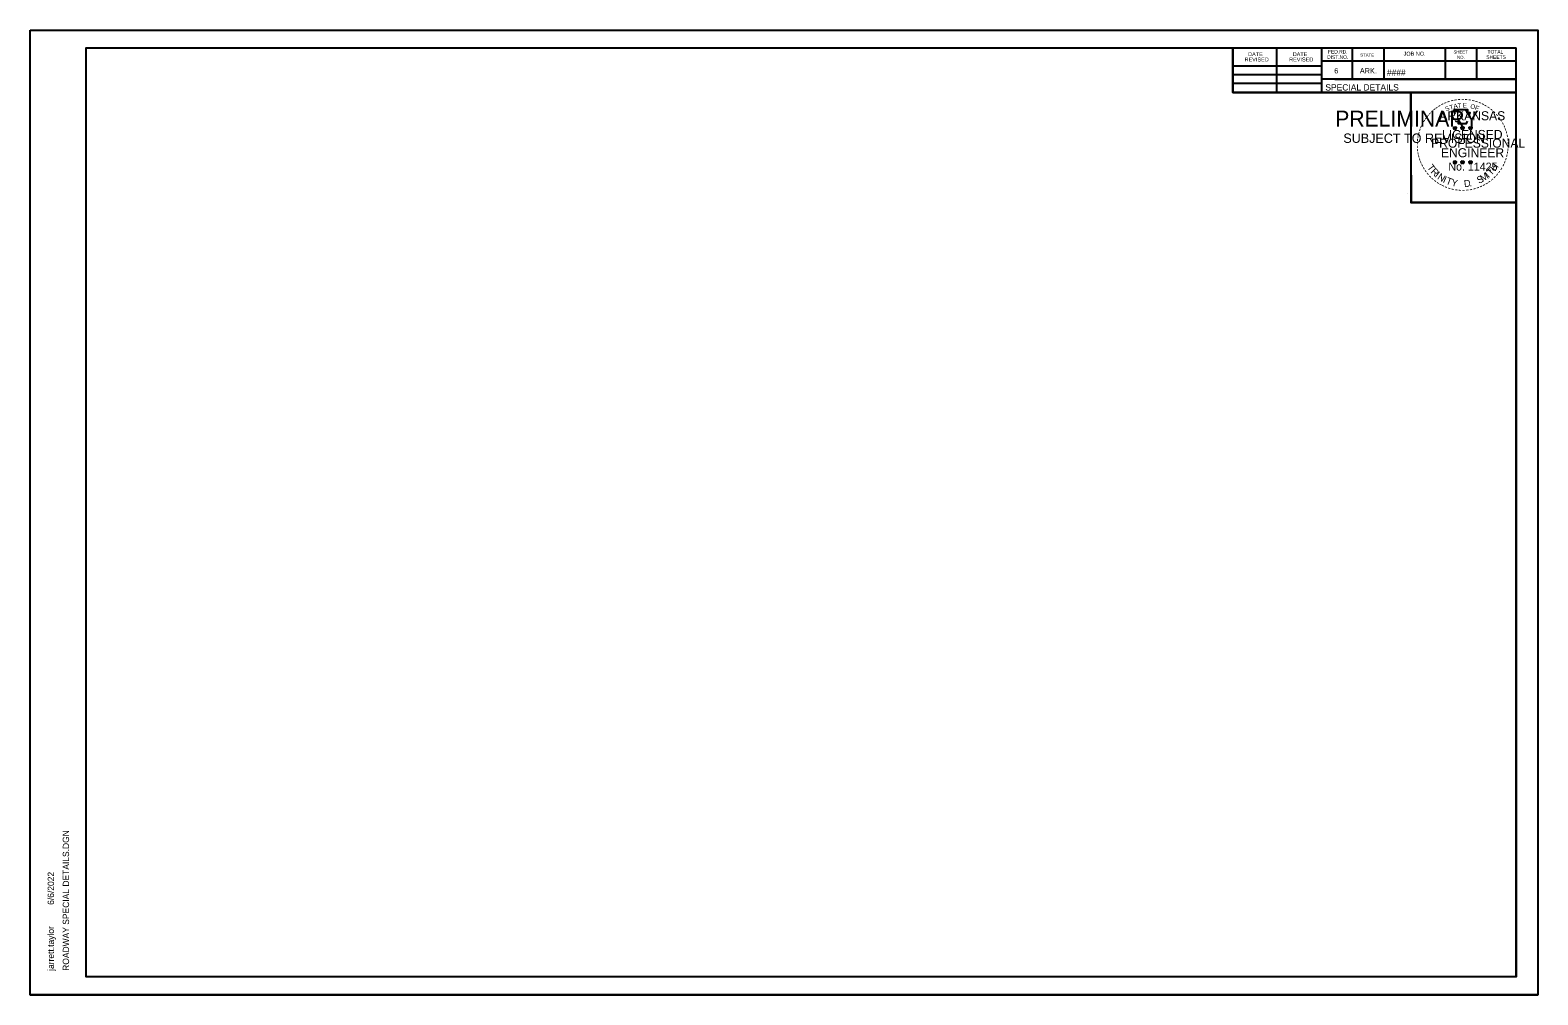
# Model space of a CAD drawing. Extents: x 438659 to 573674, y 10724 to 98600.
# Drawn here: x 532438.7 to 532605.4, y 52572.9 to 52679.6 of the extents above; entities that cross this region are included whole.
import ezdxf

# ---------------------------------------------------------------- set-up
doc = ezdxf.new("R2010")
doc.units = 0
for name, color, linetype in [('R_Grid', 7, 'Continuous'), ('R_Horz Alg', 7, 'Continuous'), ('R_Horz Alg Annot', 7, 'Continuous'), ('R_MOT', 7, 'Continuous')]:
    doc.layers.add(name, color=color, linetype=linetype)

msp = doc.modelspace()

# ---------------------------------------------------------------- linework, layer by layer
at = {"layer": 'R_Grid'}
for p, q in [((532444.94, 52677.62), (532603.03, 52677.62)), ((532444.94, 52574.89), (532444.94, 52677.62)), ((532521.2, 52677.49), (532521.2, 52677.49)), ((532521.2, 52677.49), (532521.2, 52677.49)), ((532571.71, 52672.68), (532571.71, 52677.62)), ((532576.55, 52672.68), (532576.55, 52677.62)), ((532581.48, 52677.62), (532581.48, 52672.68)), ((532584.9, 52677.62), (532584.9, 52674.15)), ((532588.37, 52677.62), (532588.37, 52674.15)), ((532595.16, 52677.62), (532595.16, 52674.15)), ((532598.63, 52677.62), (532598.63, 52674.15)), ((532603.03, 52574.89), (532603.03, 52677.62)), ((532603.03, 52676.15), (532581.48, 52676.15)), ((532603.03, 52676.16), (532603.03, 52676.16)), ((532571.71, 52675.61), (532581.48, 52675.61)), ((532571.71, 52674.68), (532581.48, 52674.68)), ((532603.03, 52674.15), (532581.48, 52674.15)), ((532582.96, 52674.15), (532603.03, 52674.15)), ((532571.71, 52673.71), (532581.48, 52673.71)), ((532603.03, 52672.68), (532571.71, 52672.68)), ((532444.94, 52574.89), (532444.94, 52574.89)), ((532603.03, 52574.89), (532444.94, 52574.89))]:
    msp.add_line(p, q, dxfattribs=at)
at = {"layer": 'R_Horz Alg'}
for p, q in [((532438.74, 52679.57), (532605.41, 52679.57)), ((532591.05, 52661.45), (532591.05, 52661.45)), ((532438.74, 52572.9), (532605.41, 52572.9))]:
    msp.add_line(p, q, dxfattribs=at)
for points in [[(532438.74, 52679.57), (532605.41, 52679.57), (532605.41, 52572.89), (532438.74, 52572.89)], [(532561.9, 52677.62), (532571.71, 52677.62), (532571.71, 52672.68), (532579.77, 52672.68), (532591.37, 52672.68), (532591.37, 52660.51), (532603.03, 52660.51), (532603.03, 52574.89), (532444.94, 52574.89), (532444.94, 52677.62)], [(532591.37, 52672.68), (532602.97, 52672.68), (532603.03, 52660.51), (532591.43, 52660.51)]]:
    msp.add_lwpolyline(points, close=True, dxfattribs=at)
at = {"layer": 'R_MOT'}
for p, q in [((532596.08, 52668.81), (532596.25, 52668.75)), ((532596.08, 52668.81), (532596.2, 52668.78)), ((532596.08, 52668.81), (532596.2, 52668.75)), ((532596.14, 52668.6), (532596.25, 52668.75)), ((532596.14, 52668.6), (532596.21, 52668.72)), ((532596.14, 52668.6), (532596.25, 52668.71)), ((532596.25, 52668.93), (532596.23, 52668.81)), ((532596.25, 52668.75), (532596.25, 52668.93)), ((532596.25, 52668.93), (532596.28, 52668.81)), ((532596.42, 52668.81), (532596.25, 52668.75)), ((532596.36, 52668.6), (532596.25, 52668.75)), ((532596.36, 52668.6), (532596.25, 52668.71)), ((532596.42, 52668.81), (532596.28, 52668.78)), ((532596.36, 52668.6), (532596.29, 52668.75)), ((532596.42, 52668.81), (532596.32, 52668.76)), ((532596.91, 52668.81), (532597.09, 52668.75)), ((532596.91, 52668.81), (532597.04, 52668.78)), ((532596.91, 52668.81), (532597.03, 52668.75)), ((532596.98, 52668.6), (532597.09, 52668.75)), ((532596.98, 52668.6), (532597.04, 52668.72)), ((532596.98, 52668.6), (532597.09, 52668.71)), ((532597.09, 52668.93), (532597.07, 52668.81)), ((532597.09, 52668.75), (532597.09, 52668.93)), ((532597.09, 52668.93), (532597.11, 52668.81)), ((532597.26, 52668.81), (532597.09, 52668.75)), ((532597.19, 52668.6), (532597.09, 52668.75)), ((532597.19, 52668.6), (532597.09, 52668.71)), ((532597.26, 52668.81), (532597.12, 52668.78)), ((532597.19, 52668.6), (532597.12, 52668.75)), ((532597.26, 52668.81), (532597.16, 52668.76)), ((532597.79, 52668.8), (532597.97, 52668.74)), ((532597.79, 52668.8), (532597.92, 52668.78)), ((532597.79, 52668.8), (532597.91, 52668.74)), ((532597.86, 52668.6), (532597.97, 52668.74)), ((532597.86, 52668.6), (532597.92, 52668.72)), ((532597.86, 52668.6), (532597.97, 52668.7)), ((532597.97, 52668.93), (532597.95, 52668.8)), ((532597.97, 52668.74), (532597.97, 52668.93)), ((532597.97, 52668.93), (532597.99, 52668.8)), ((532598.14, 52668.8), (532597.97, 52668.74)), ((532598.07, 52668.6), (532597.97, 52668.74)), ((532598.07, 52668.6), (532597.97, 52668.7)), ((532598.14, 52668.8), (532598, 52668.78)), ((532598.07, 52668.6), (532598.01, 52668.74)), ((532598.14, 52668.8), (532598.04, 52668.75)), ((532596.07, 52665.02), (532596.25, 52664.96)), ((532596.07, 52665.02), (532596.2, 52665)), ((532596.07, 52665.02), (532596.19, 52664.96)), ((532596.14, 52664.82), (532596.25, 52664.96)), ((532596.14, 52664.82), (532596.2, 52664.94)), ((532596.14, 52664.82), (532596.25, 52664.92)), ((532596.25, 52665.15), (532596.23, 52665.02)), ((532596.25, 52664.96), (532596.25, 52665.15)), ((532596.25, 52665.15), (532596.27, 52665.02)), ((532596.42, 52665.02), (532596.25, 52664.96)), ((532596.36, 52664.82), (532596.25, 52664.96)), ((532596.36, 52664.82), (532596.25, 52664.92)), ((532596.42, 52665.02), (532596.28, 52665)), ((532596.36, 52664.82), (532596.29, 52664.96)), ((532596.42, 52665.02), (532596.32, 52664.97)), ((532596.91, 52665.02), (532597.08, 52664.96)), ((532596.91, 52665.02), (532597.04, 52665)), ((532596.91, 52665.02), (532597.03, 52664.96)), ((532596.98, 52664.82), (532597.08, 52664.96)), ((532596.98, 52664.82), (532597.04, 52664.94)), ((532596.98, 52664.82), (532597.08, 52664.92)), ((532597.08, 52665.15), (532597.06, 52665.02)), ((532597.08, 52664.96), (532597.08, 52665.15)), ((532597.08, 52665.15), (532597.11, 52665.02)), ((532597.26, 52665.02), (532597.08, 52664.96)), ((532597.19, 52664.82), (532597.08, 52664.96)), ((532597.19, 52664.82), (532597.08, 52664.92)), ((532597.26, 52665.02), (532597.11, 52665)), ((532597.19, 52664.82), (532597.12, 52664.96)), ((532597.26, 52665.02), (532597.16, 52664.97)), ((532597.79, 52665.01), (532597.97, 52664.96)), ((532597.79, 52665.01), (532597.92, 52664.99)), ((532597.79, 52665.01), (532597.91, 52664.95)), ((532597.86, 52664.81), (532597.97, 52664.96)), ((532597.86, 52664.81), (532597.92, 52664.93)), ((532597.86, 52664.81), (532597.97, 52664.92)), ((532597.97, 52665.14), (532597.95, 52665.02)), ((532597.97, 52664.96), (532597.97, 52665.14)), ((532597.97, 52665.14), (532597.99, 52665.02)), ((532598.14, 52665.01), (532597.97, 52664.96)), ((532598.07, 52664.81), (532597.97, 52664.96)), ((532598.07, 52664.81), (532597.97, 52664.92)), ((532598.14, 52665.01), (532598, 52664.99)), ((532598.07, 52664.81), (532598.01, 52664.96)), ((532598.14, 52665.01), (532598.04, 52664.96))]:
    msp.add_line(p, q, dxfattribs=at)
for points in [[(532596.1, 52670.75), (532596.23, 52670.33)], [(532597.85, 52670.28), (532597.92, 52670.43), (532597.58, 52670.41), (532597.66, 52670.75), (532596.1, 52670.75)], [(532596.34, 52669.53), (532596.34, 52669.49), (532596.62, 52669.48), (532596.6, 52669.24), (532597.53, 52669.24), (532597.63, 52669.51)], [(532596.25, 52668.93), (532596.36, 52668.6), (532596.08, 52668.81), (532596.42, 52668.81), (532596.14, 52668.6), (532596.25, 52668.93)], [(532597.09, 52668.93), (532597.19, 52668.6), (532596.91, 52668.81), (532597.26, 52668.81), (532596.98, 52668.6), (532597.09, 52668.93)], [(532597.97, 52668.93), (532598.07, 52668.6), (532597.79, 52668.8), (532598.14, 52668.8), (532597.86, 52668.6), (532597.97, 52668.93)], [(532596.25, 52665.15), (532596.36, 52664.82), (532596.07, 52665.02), (532596.42, 52665.02), (532596.14, 52664.82), (532596.25, 52665.15)], [(532597.08, 52665.15), (532597.19, 52664.82), (532596.91, 52665.02), (532597.26, 52665.02), (532596.98, 52664.82), (532597.08, 52665.15)], [(532597.97, 52665.14), (532598.07, 52664.81), (532597.79, 52665.01), (532598.14, 52665.01), (532597.86, 52664.81), (532597.97, 52665.14)]]:
    msp.add_lwpolyline(points, dxfattribs=at)
for centre, radius in [((532596.25, 52668.75), 0.0861), ((532596.25, 52668.75), 0.0723), ((532596.25, 52668.75), 0.0579), ((532596.25, 52668.75), 0.0495), ((532596.25, 52668.75), 0.0374), ((532596.25, 52668.75), 0.0248), ((532596.25, 52668.75), 0.0148), ((532597.09, 52668.75), 0.0861), ((532597.09, 52668.75), 0.0723), ((532597.09, 52668.75), 0.0579), ((532597.09, 52668.75), 0.0495), ((532597.09, 52668.75), 0.0374), ((532597.09, 52668.75), 0.0248), ((532597.09, 52668.75), 0.0148), ((532597.97, 52668.74), 0.0861), ((532597.97, 52668.74), 0.0723), ((532597.97, 52668.74), 0.0579), ((532597.97, 52668.74), 0.0495), ((532597.97, 52668.74), 0.0374), ((532597.97, 52668.74), 0.0248), ((532597.97, 52668.74), 0.0148), ((532596.25, 52664.96), 0.0861), ((532596.25, 52664.96), 0.0723), ((532596.25, 52664.96), 0.0579), ((532596.25, 52664.96), 0.0495), ((532596.25, 52664.96), 0.0374), ((532596.25, 52664.96), 0.0248), ((532596.25, 52664.96), 0.0148), ((532597.08, 52664.96), 0.0861), ((532597.08, 52664.96), 0.0723), ((532597.08, 52664.96), 0.0579), ((532597.08, 52664.96), 0.0495), ((532597.08, 52664.96), 0.0374), ((532597.08, 52664.96), 0.0248), ((532597.08, 52664.96), 0.0148), ((532597.97, 52664.96), 0.0861), ((532597.97, 52664.96), 0.0723), ((532597.97, 52664.96), 0.0579), ((532597.97, 52664.96), 0.0495), ((532597.97, 52664.96), 0.0374), ((532597.97, 52664.96), 0.0248), ((532597.97, 52664.96), 0.0148)]:
    msp.add_circle(centre, radius, dxfattribs=at)

# ---------------------------------------------------------------- texts
at = {"layer": 'R_Grid'}
for s, height, p in [('REVISED', 0.44, (532572.99, 52676.1)), ('DATE', 0.44, (532573.38, 52676.69)), ('REVISED', 0.44, (532577.92, 52676.1)), ('DATE', 0.44, (532578.31, 52676.69)), ('DIST.NO.', 0.391, (532582.12, 52676.39)), ('FED.RD.', 0.391, (532582.22, 52676.98)), ('STATE', 0.342, (532585.78, 52676.64)), ('JOB NO.', 0.44, (532590.57, 52676.74)), ('SHEET', 0.342, (532596.09, 52676.98)), ('NO.', 0.342, (532596.48, 52676.39)), ('SHEETS', 0.391, (532599.71, 52676.39)), ('TOTAL', 0.391, (532599.85, 52676.98)), ('6', 0.586, (532582.9, 52674.78)), ('ARK.', 0.586, (532585.73, 52674.78)), ('####', 0.7, (532588.72, 52674.52)), ('SPECIAL DETAILS', 0.7, (532581.92, 52672.89))]:
    msp.add_text(s, height=height, dxfattribs=at).set_placement(p)
for s, p in [('ROADWAY SPECIAL DETAILS.DGN', (532443.04, 52575.55)), ('6/6/2022', (532441.37, 52582.85)), ('jarrett.taylor', (532441.37, 52575.55))]:
    msp.add_text(s, height=0.7, rotation=90, dxfattribs=at).set_placement(p)
at = {"layer": 'R_Horz Alg Annot'}
for s, height, p in [('PRELIMINARY', 1.75, (532583.01, 52668.91)), ('DWB', 0.005, (532583.38, 52669.83)), ('SUBJECT TO REVISION', 1.0376, (532583.91, 52667.1))]:
    msp.add_text(s, height=height, dxfattribs=at).set_placement(p)
at = {"layer": 'R_MOT'}
for s, height, rotation, p in [('-', 0.8, 38.9507, (532594.01, 52670.44)), ('-', 0.8, 36.2317, (532594.25, 52670.63)), ('-', 0.8, 34.0636, (532594.54, 52670.83)), ('-', 0.8, 28.7918, (532594.84, 52671.02)), ('-', 0.8, 24.3072, (532595.15, 52671.17)), ('S', 0.5, 21.594, (532595.27, 52670.58)), ('-', 0.8, 19.1761, (532595.47, 52671.31)), ('T', 0.5, 16.4036, (532595.73, 52670.75)), ('-', 0.8, 13.6302, (532595.85, 52671.43)), ('A', 0.5, 11.2132, (532596.14, 52670.88)), ('-', 0.8, 10.2193, (532596.19, 52671.51)), ('T', 0.5, 6.0228, (532596.57, 52670.96)), ('-', 0.8, 5.8968, (532596.55, 52671.57)), ('-', 0.8, 0.1862, (532596.94, 52671.6)), ('E', 0.5, 0.8323, (532597.12, 52671.01)), ('-', 0.8, 357.743, (532597.3, 52671.59)), ('-', 0.8, 352.1617, (532597.67, 52671.57)), ('O', 0.5, 350.4515, (532597.92, 52670.91)), ('-', 0.8, 347.2049, (532598.03, 52671.51)), ('F', 0.5, 340.0707, (532598.4, 52670.79)), ('-', 0.8, 342.3362, (532598.35, 52671.43)), ('-', 0.8, 337.8551, (532598.71, 52671.32)), ('-', 0.8, 334.1211, (532599.03, 52671.19)), ('-', 0.8, 329.6409, (532599.32, 52671.04)), ('-', 0.8, 325.8627, (532599.64, 52670.86)), ('-', 0.8, 320.5297, (532599.95, 52670.65)), ('-', 0.8, 62.8713, (532592.84, 52668.9)), ('-', 0.8, 58.0706, (532593, 52669.21)), ('-', 0.8, 54.2325, (532593.16, 52669.47)), ('-', 0.8, 50.6142, (532593.37, 52669.75)), ('-', 0.8, 48.4231, (532593.57, 52670)), ('-', 0.8, 42.9622, (532593.8, 52670.24)), ('-', 0.8, 315.5786, (532600.24, 52670.41)), ('-', 0.8, 309.8797, (532600.53, 52670.13)), ('-', 0.8, 306.6522, (532600.79, 52669.83)), ('-', 0.7, 303.6753, (532601.03, 52669.55)), ('-', 0.8, 299.6684, (532601.19, 52669.24)), ('-', 0.8, 85.1863, (532592.4, 52667.22)), ('-', 0.8, 81.2013, (532592.44, 52667.57)), ('-', 0.8, 75.461, (532592.51, 52667.92)), ('-', 0.8, 72.3945, (532592.61, 52668.28)), ('-', 0.8, 67.7743, (532592.71, 52668.59)), ('-', 0.8, 294.6628, (532601.36, 52668.94)), ('-', 0.8, 290.5728, (532601.48, 52668.65)), ('-', 0.8, 285.1233, (532601.6, 52668.36)), ('-', 0.8, 280.5493, (532601.7, 52667.99)), ('-', 0.8, 276.5962, (532601.78, 52667.6)), ('-', 0.8, 94.1959, (532592.41, 52666.51)), ('-', 0.8, 89.0622, (532592.39, 52666.87)), ('-', 0.8, 98.9479, (532592.44, 52666.17)), ('-', 0.8, 101.7149, (532592.51, 52665.81)), ('-', 0.8, 255.7626, (532601.73, 52665.93)), ('-', 0.8, 260.9953, (532601.78, 52666.27)), ('-', 0.8, 263.5172, (532601.82, 52666.59)), ('-', 0.8, 274.3301, (532601.81, 52667.24)), ('-', 0.8, 269.9407, (532601.83, 52666.93)), ('-', 0.8, 105.4578, (532592.59, 52665.51)), ('-', 0.8, 109.0874, (532592.7, 52665.19)), ('-', 0.8, 114.0643, (532592.83, 52664.9)), ('-', 0.8, 115.7289, (532592.98, 52664.59)), ('-', 0.8, 120.4471, (532593.16, 52664.29)), ('T', 0.77, 306.0406, (532593.13, 52664.38)), ('R', 0.77, 314.005, (532593.51, 52663.86)), ('T', 0.77, 46.6444, (532600.24, 52663.43)), ('H', 0.77, 54.6088, (532600.69, 52663.9)), ('-', 0.8, 239.0712, (532601.2, 52664.54)), ('-', 0.8, 244.6197, (532601.4, 52664.92)), ('-', 0.8, 247.8887, (532601.53, 52665.23)), ('-', 0.8, 252.8681, (532601.64, 52665.57)), ('-', 0.8, 125.8934, (532593.36, 52664.01)), ('-', 0.8, 130.7181, (532593.59, 52663.74)), ('-', 0.8, 134.2238, (532593.85, 52663.46)), ('-', 0.8, 138.9338, (532594.11, 52663.23)), ('-', 0.8, 144.6463, (532594.39, 52663.03)), ('I', 0.77, 321.9694, (532593.96, 52663.39)), ('-', 0.8, 148.0898, (532594.67, 52662.84)), ('N', 0.77, 326.5002, (532594.24, 52663.16)), ('-', 0.8, 151.5704, (532594.96, 52662.68)), ('I', 0.77, 335.3603, (532594.85, 52662.76)), ('T', 0.77, 339.8912, (532595.18, 52662.6)), ('Y', 0.77, 347.8556, (532595.79, 52662.38)), ('D', 0.77, 6.3969, (532597.28, 52662.2)), ('S', 0.77, 26.9312, (532598.9, 52662.56)), ('M', 0.77, 32.6563, (532599.32, 52662.77)), ('-', 0.8, 207.3568, (532599.46, 52662.79)), ('I', 0.77, 42.1136, (532599.96, 52663.19)), ('-', 0.8, 212.2491, (532599.74, 52662.96)), ('-', 0.8, 215.7363, (532600.01, 52663.16)), ('-', 0.8, 221.0851, (532600.28, 52663.39)), ('-', 0.8, 225.7653, (532600.54, 52663.65)), ('-', 0.8, 231.2538, (532600.78, 52663.93)), ('-', 0.8, 233.8452, (532601, 52664.21)), ('-', 0.8, 154.6002, (532595.22, 52662.56)), ('-', 0.8, 158.5612, (532595.53, 52662.43)), ('-', 0.8, 162.7983, (532595.88, 52662.32)), ('-', 0.8, 167.5555, (532596.23, 52662.24)), ('-', 0.8, 173.1155, (532596.62, 52662.19)), ('-', 0.8, 176.5183, (532596.99, 52662.16)), ('-', 0.8, 181.5918, (532597.37, 52662.17)), ('-', 0.8, 185.8167, (532597.77, 52662.21)), ('-', 0.8, 191.2858, (532598.14, 52662.27)), ('.', 0.77, 13.7642, (532597.88, 52662.26)), ('-', 0.8, 195.4743, (532598.5, 52662.37)), ('-', 0.8, 200.7184, (532598.84, 52662.5)), ('-', 0.8, 204.2516, (532599.15, 52662.63))]:
    msp.add_text(s, height=height, rotation=rotation, dxfattribs=at).set_placement(p)
for s, height, p in [('ARKANSAS', 1, (532594.52, 52669.6)), ('PROFESSIONAL', 1, (532593.61, 52666.57)), ('LICENSED', 1, (532594.82, 52667.53)), ('DWB', 0.005, (532596.24, 52668.75)), ('DWB', 0.005, (532597.08, 52668.75)), ('DWB', 0.005, (532597.96, 52668.74)), ('ENGINEER', 1, (532594.7, 52665.51)), ('No. 11425', 0.879, (532595.52, 52664.04)), ('DWB', 0.005, (532596.24, 52664.96)), ('DWB', 0.005, (532597.08, 52664.96)), ('DWB', 0.005, (532597.96, 52664.96))]:
    msp.add_text(s, height=height, dxfattribs=at).set_placement(p)

doc.saveas('drawing.dxf')
